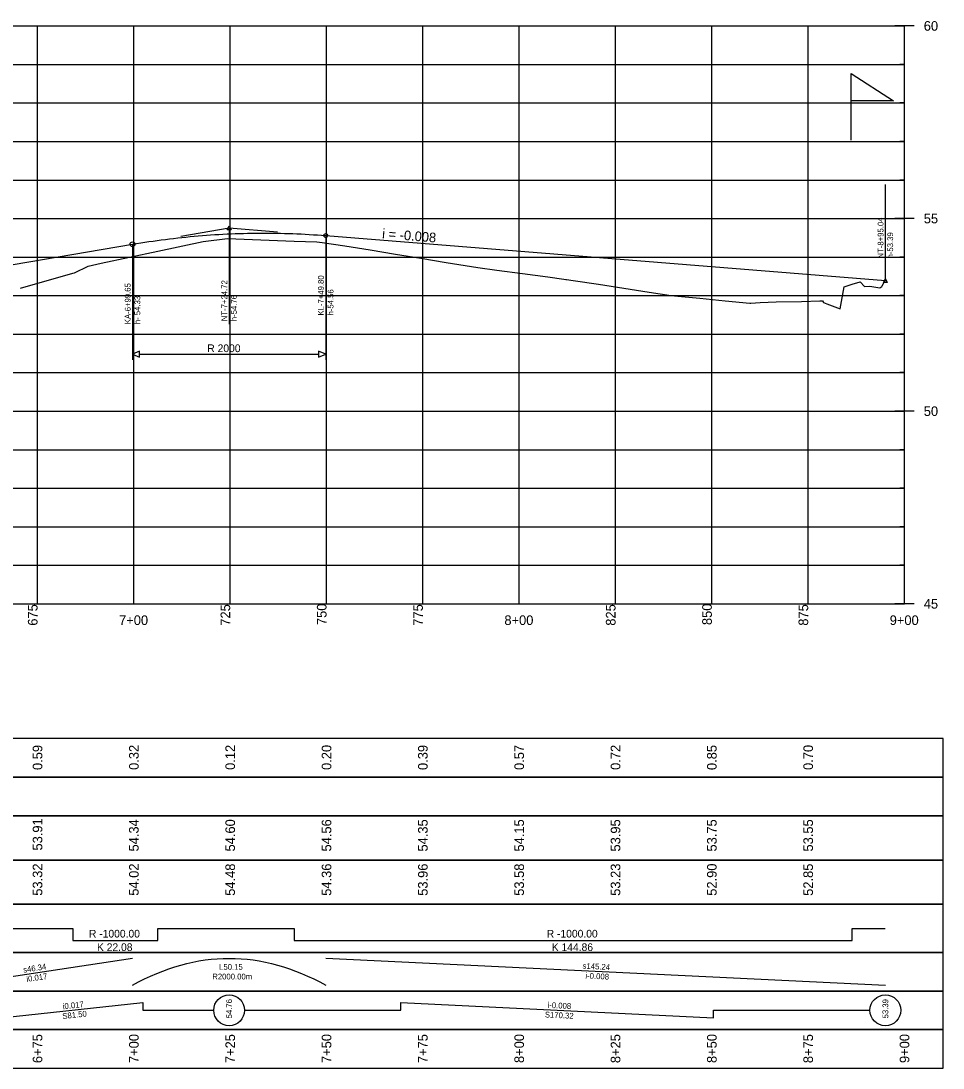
# Model space of a CAD drawing. Extents: x 655100 to 703495, y 6445581 to 6476602.
# Drawn here: x 669980 to 670219.3, y 6465749.1 to 6466020.9 of the extents above; entities that cross this region are included whole.
import ezdxf

# ---------------------------------------------------------------- set-up
doc = ezdxf.new("R2010")
doc.units = 0
for name, color, linetype in [('54', 7, 'Continuous'), ('Level 25', 7, 'Continuous'), ('Level 6', 7, 'Continuous'), ('Profile', 7, 'Continuous'), ('Profile Annotation', 7, 'Continuous'), ('Prop Vertical Alignment', 7, 'Continuous'), ('Prop_Benching', 7, 'Continuous')]:
    doc.layers.add(name, color=color, linetype=linetype)

msp = doc.modelspace()

# ---------------------------------------------------------------- linework, layer by layer
at = {"layer": '54'}
for points in [[(669299.3, 6465824.57), (670219.3, 6465824.57), (670219.3, 6465834.57), (669299.3, 6465834.57)], [(669299.3, 6465814.57), (670219.3, 6465814.57), (670219.3, 6465824.57), (669299.3, 6465824.57)], [(669299.3, 6465803.07), (670219.3, 6465803.07), (670219.3, 6465814.57), (669299.3, 6465814.57)], [(669299.3, 6465791.57), (670219.3, 6465791.57), (670219.3, 6465803.07), (669299.3, 6465803.07)], [(669299.3, 6465779.07), (670219.3, 6465779.07), (670219.3, 6465791.57), (669299.3, 6465791.57)], [(669299.3, 6465769.07), (670219.3, 6465769.07), (670219.3, 6465779.07), (669299.3, 6465779.07)], [(669299.3, 6465759.07), (670219.3, 6465759.07), (670219.3, 6465769.07), (669299.3, 6465769.07)], [(669299.3, 6465749.07), (670219.3, 6465749.07), (670219.3, 6465759.07), (669299.3, 6465759.07)]]:
    msp.add_lwpolyline(points, close=True, dxfattribs=at)
for points in [[(669984.3, 6465834.57), (669984.3, 6465834.57)], [(670009.3, 6465834.57), (670009.3, 6465834.57)], [(670034.3, 6465834.57), (670034.3, 6465834.57)], [(670059.3, 6465834.57), (670059.3, 6465834.57)], [(670084.3, 6465834.57), (670084.3, 6465834.57)], [(670109.3, 6465834.57), (670109.3, 6465834.57)], [(670134.3, 6465834.57), (670134.3, 6465834.57)], [(670159.3, 6465834.57), (670159.3, 6465834.57)], [(670184.3, 6465834.57), (670184.3, 6465834.57)], [(670209.3, 6465834.57), (670209.3, 6465834.57)], [(669984.3, 6465824.57), (669984.3, 6465824.57)], [(670009.3, 6465824.57), (670009.3, 6465824.57)], [(670034.3, 6465824.57), (670034.3, 6465824.57)], [(670059.3, 6465824.57), (670059.3, 6465824.57)], [(670084.3, 6465824.57), (670084.3, 6465824.57)], [(670109.3, 6465824.57), (670109.3, 6465824.57)], [(670134.3, 6465824.57), (670134.3, 6465824.57)], [(670159.3, 6465824.57), (670159.3, 6465824.57)], [(670184.3, 6465824.57), (670184.3, 6465824.57)], [(670209.3, 6465824.57), (670209.3, 6465824.57)], [(669984.3, 6465814.57), (669984.3, 6465814.57)], [(670009.3, 6465814.57), (670009.3, 6465814.57)], [(670034.3, 6465814.57), (670034.3, 6465814.57)], [(670059.3, 6465814.57), (670059.3, 6465814.57)], [(670084.3, 6465814.57), (670084.3, 6465814.57)], [(670109.3, 6465814.57), (670109.3, 6465814.57)], [(670134.3, 6465814.57), (670134.3, 6465814.57)], [(670159.3, 6465814.57), (670159.3, 6465814.57)], [(670184.3, 6465814.57), (670184.3, 6465814.57)], [(670209.3, 6465814.57), (670209.3, 6465814.57)], [(669984.3, 6465803.07), (669984.3, 6465803.07)], [(670009.3, 6465803.07), (670009.3, 6465803.07)], [(670034.3, 6465803.07), (670034.3, 6465803.07)], [(670059.3, 6465803.07), (670059.3, 6465803.07)], [(670084.3, 6465803.07), (670084.3, 6465803.07)], [(670109.3, 6465803.07), (670109.3, 6465803.07)], [(670134.3, 6465803.07), (670134.3, 6465803.07)], [(670159.3, 6465803.07), (670159.3, 6465803.07)], [(670184.3, 6465803.07), (670184.3, 6465803.07)], [(670209.3, 6465803.07), (670209.3, 6465803.07)], [(669993.44, 6465791.57), (669993.44, 6465791.57)], [(670015.52, 6465791.57), (670015.52, 6465791.57)], [(670050.86, 6465791.57), (670050.86, 6465791.57)], [(670195.72, 6465791.57), (670195.72, 6465791.57)], [(670204.27, 6465791.57), (670204.27, 6465791.57)], [(670008.95, 6465779.07), (670008.95, 6465779.07)], [(670059.1, 6465779.07), (670059.1, 6465779.07)], [(670204.34, 6465779.07), (670204.34, 6465779.07)], [(670008.95, 6465769.07), (670008.95, 6465769.07)], [(670059.1, 6465769.07), (670059.1, 6465769.07)], [(670204.34, 6465769.07), (670204.34, 6465769.07)], [(669984.3, 6465759.07), (669984.3, 6465759.07)], [(670009.3, 6465759.07), (670009.3, 6465759.07)], [(670034.3, 6465759.07), (670034.3, 6465759.07)], [(670059.3, 6465759.07), (670059.3, 6465759.07)], [(670084.3, 6465759.07), (670084.3, 6465759.07)], [(670109.3, 6465759.07), (670109.3, 6465759.07)], [(670134.3, 6465759.07), (670134.3, 6465759.07)], [(670159.3, 6465759.07), (670159.3, 6465759.07)], [(670184.3, 6465759.07), (670184.3, 6465759.07)], [(670209.3, 6465759.07), (670209.3, 6465759.07)]]:
    msp.add_lwpolyline(points, dxfattribs=at)
at = {"layer": 'Level 25'}
msp.add_lwpolyline([(670195.42, 6465989.88), (670195.42, 6466007.24), (670206.43, 6466000.16), (670195.41, 6466000.15)], dxfattribs=at)
at = {"layer": 'Level 6'}
msp.add_lwpolyline([(669979.86, 6465951.5), (669993.44, 6465955.39), (669993.92, 6465955.52), (669997.41, 6465957.23), (670000.8, 6465957.97), (670008.16, 6465959.55), (670015.52, 6465961.11), (670027.27, 6465963.57), (670033.61, 6465964.38), (670050.86, 6465963.72), (670056.77, 6465963.49), (670057.44, 6465963.43), (670058.17, 6465963.36), (670061.11, 6465962.96), (670064.03, 6465962.49), (670070.61, 6465961.42), (670077.19, 6465960.34), (670083.78, 6465959.27), (670090.36, 6465958.18), (670096.95, 6465957.1), (670098.54, 6465956.84), (670103.53, 6465956.18), (670110.12, 6465955.3), (670116.7, 6465954.42), (670120.89, 6465953.86), (670121.41, 6465953.79), (670121.57, 6465953.77), (670123.29, 6465953.51), (670129.87, 6465952.5), (670136.46, 6465951.5), (670143.04, 6465950.5), (670148.75, 6465949.63), (670149.62, 6465949.52), (670150.44, 6465949.41), (670156.21, 6465948.87), (670162.79, 6465948.24), (670169.18, 6465947.63), (670169.38, 6465947.64), (670171.83, 6465947.82), (670175.96, 6465947.92), (670182.55, 6465948.07), (670187.32, 6465948.18), (670187.98, 6465948.22), (670188.26, 6465947.74), (670189.13, 6465947.42), (670192.6, 6465946.12), (670193.67, 6465951.83), (670194.97, 6465952.27), (670195.72, 6465952.5), (670197.83, 6465953.18), (670198.88, 6465951.95), (670200.34, 6465952.04), (670202.89, 6465951.61), (670203.39, 6465951.91), (670203.49, 6465952.07), (670204.27, 6465953.46)], dxfattribs=at)
at = {"layer": 'Profile'}
for p, q in [((669309.3, 6466019.57), (670209.3, 6466019.57)), ((669309.3, 6466019.57), (670209.3, 6466019.57)), ((669984.3, 6465869.57), (669984.3, 6466019.57)), ((670009.3, 6465869.57), (670009.3, 6466019.57)), ((670034.3, 6465869.57), (670034.3, 6466019.57)), ((670059.3, 6465869.57), (670059.3, 6466019.57)), ((670084.3, 6465869.57), (670084.3, 6466019.57)), ((670109.3, 6465869.57), (670109.3, 6466019.57)), ((670134.3, 6465869.57), (670134.3, 6466019.57)), ((670159.3, 6465869.57), (670159.3, 6466019.57)), ((670184.3, 6465869.57), (670184.3, 6466019.57)), ((670211.8, 6466019.57), (670206.8, 6466019.57)), ((670211.8, 6466019.57), (670206.8, 6466019.57)), ((670209.3, 6465869.57), (670209.3, 6466019.57)), ((669309.3, 6466009.57), (670209.3, 6466009.57)), ((670209.3, 6466009.57), (670208.05, 6466009.57)), ((669309.3, 6465999.57), (670209.3, 6465999.57)), ((670209.3, 6465999.57), (670208.05, 6465999.57)), ((669309.3, 6465989.57), (670209.3, 6465989.57)), ((670209.3, 6465989.57), (670208.05, 6465989.57)), ((669309.3, 6465979.57), (670209.3, 6465979.57)), ((670209.3, 6465979.57), (670208.05, 6465979.57)), ((669309.3, 6465969.57), (670209.3, 6465969.57)), ((670211.8, 6465969.57), (670206.8, 6465969.57)), ((669309.3, 6465959.57), (670209.3, 6465959.57)), ((670209.3, 6465959.57), (670208.05, 6465959.57)), ((669309.3, 6465949.57), (670209.3, 6465949.57)), ((670209.3, 6465949.57), (670208.05, 6465949.57)), ((669309.3, 6465939.57), (670209.3, 6465939.57)), ((670209.3, 6465939.57), (670208.05, 6465939.57)), ((669309.3, 6465929.57), (670209.3, 6465929.57)), ((670209.3, 6465929.57), (670208.05, 6465929.57)), ((669309.3, 6465919.57), (670209.3, 6465919.57)), ((670211.8, 6465919.57), (670206.8, 6465919.57)), ((669309.3, 6465909.57), (670209.3, 6465909.57)), ((670209.3, 6465909.57), (670208.05, 6465909.57)), ((669309.3, 6465899.57), (670209.3, 6465899.57)), ((670209.3, 6465899.57), (670208.05, 6465899.57)), ((669309.3, 6465889.57), (670209.3, 6465889.57)), ((670209.3, 6465889.57), (670208.05, 6465889.57)), ((669309.3, 6465879.57), (670209.3, 6465879.57)), ((670209.3, 6465879.57), (670208.05, 6465879.57)), ((669309.3, 6465869.57), (670209.3, 6465869.57)), ((670211.8, 6465869.57), (670206.8, 6465869.57))]:
    msp.add_line(p, q, dxfattribs=at)
at = {"layer": 'Profile Annotation'}
for points in [[(669648.62, 6465785.32), (669796.34, 6465785.32), (669796.34, 6465782.2), (669823.91, 6465782.2), (669823.91, 6465785.32), (669845.97, 6465785.32), (669845.97, 6465788.45), (669881.07, 6465788.45), (669881.07, 6465785.32), (669930.74, 6465785.32), (669930.74, 6465782.2), (669941.56, 6465782.2), (669941.56, 6465785.32), (669993.44, 6465785.32), (669993.44, 6465782.2), (670015.52, 6465782.2), (670015.52, 6465785.32), (670050.86, 6465785.32), (670050.86, 6465782.2), (670195.72, 6465782.2), (670195.72, 6465785.32), (670204.27, 6465785.32)], [(669962.61, 6465770.57), (670008.95, 6465777.57)], [(670008.95, 6465770.57), (670010.52, 6465771.42), (670012.09, 6465772.21), (670013.65, 6465772.95), (670015.22, 6465773.64), (670016.79, 6465774.26), (670018.35, 6465774.84), (670019.92, 6465775.36), (670021.49, 6465775.82), (670023.06, 6465776.23), (670024.62, 6465776.59), (670026.19, 6465776.89), (670027.76, 6465777.14), (670029.32, 6465777.33), (670030.89, 6465777.46), (670032.46, 6465777.55), (670035.59, 6465777.55), (670037.16, 6465777.46), (670038.73, 6465777.33), (670040.29, 6465777.14), (670041.86, 6465776.89), (670043.43, 6465776.59), (670045, 6465776.23), (670046.56, 6465775.82), (670048.13, 6465775.36), (670049.7, 6465774.84), (670051.26, 6465774.26), (670052.83, 6465773.64), (670054.4, 6465772.95), (670055.97, 6465772.21), (670057.53, 6465771.42), (670059.1, 6465770.57)], [(670059.1, 6465777.57), (670204.34, 6465770.57)], [(669956.52, 6465764.07), (669974.9, 6465764.07), (669974.9, 6465762.07), (670011.65, 6465766.07), (670011.65, 6465764.07), (670030.02, 6465764.07)], [(670038.02, 6465764.07), (670078.6, 6465764.07), (670078.6, 6465766.07), (670159.76, 6465762.07), (670159.76, 6465764.07), (670200.34, 6465764.07)]]:
    msp.add_lwpolyline(points, dxfattribs=at)
for centre in [(670034.02, 6465764.07), (670204.34, 6465764.07)]:
    msp.add_circle(centre, 4, dxfattribs=at)
at = {"layer": 'Prop Vertical Alignment'}
for p, q in [((670204.34, 6465958.45), (670204.34, 6465978.45)), ((670021.49, 6465965.03), (670034.02, 6465967.17)), ((670034.02, 6465967.17), (670046.56, 6465966.16)), ((670034.02, 6465967.17), (670034.02, 6465962.17)), ((670059.1, 6465965.15), (670059.1, 6465960.15)), ((670059.1, 6465965.15), (670204.34, 6465953.45)), ((670059.1, 6465965.15), (670059.1, 6465932.9)), ((669962.61, 6465955.01), (670008.95, 6465962.9)), ((670008.95, 6465962.9), (670008.95, 6465957.9)), ((670008.95, 6465962.9), (670008.95, 6465932.9)), ((670034.02, 6465962.17), (670034.02, 6465942.17)), ((670008.95, 6465957.9), (670008.95, 6465941.4)), ((670059.1, 6465960.15), (670059.1, 6465943.65)), ((670204.34, 6465953.45), (670204.34, 6465958.45))]:
    msp.add_line(p, q, dxfattribs=at)
for points in [[(670008.95, 6465962.9), (670010.02, 6465963.08), (670011.08, 6465963.25), (670012.15, 6465963.42), (670013.22, 6465963.58), (670014.29, 6465963.74), (670015.35, 6465963.89), (670016.42, 6465964.03), (670017.49, 6465964.17), (670018.55, 6465964.3), (670019.62, 6465964.43), (670020.69, 6465964.55), (670021.75, 6465964.67), (670022.82, 6465964.78), (670023.89, 6465964.88), (670024.96, 6465964.98), (670026.02, 6465965.08), (670027.09, 6465965.16), (670028.16, 6465965.25), (670029.22, 6465965.32), (670030.29, 6465965.39), (670031.36, 6465965.46), (670032.42, 6465965.52), (670033.49, 6465965.57), (670034.56, 6465965.62), (670035.63, 6465965.66), (670036.69, 6465965.7), (670037.76, 6465965.73), (670038.83, 6465965.75), (670039.89, 6465965.77), (670040.96, 6465965.78), (670042.03, 6465965.79), (670043.09, 6465965.8), (670044.16, 6465965.79), (670045.23, 6465965.78), (670046.3, 6465965.77), (670047.36, 6465965.75), (670048.43, 6465965.72), (670049.5, 6465965.69), (670050.56, 6465965.65), (670051.63, 6465965.61), (670052.7, 6465965.56), (670053.77, 6465965.5), (670054.83, 6465965.44), (670055.9, 6465965.38), (670056.97, 6465965.31), (670058.03, 6465965.23), (670059.1, 6465965.15)], [(670010.8, 6465934.4), (670057.25, 6465934.4)]]:
    msp.add_lwpolyline(points, dxfattribs=at)
for points in [[(670034.02, 6465967.67), (670034.52, 6465966.67), (670033.52, 6465966.67)], [(670204.34, 6465953.95), (670204.84, 6465952.95), (670203.84, 6465952.95)], [(670008.95, 6465934.4), (670010.8, 6465933.63), (670010.8, 6465935.16)], [(670059.1, 6465934.4), (670057.25, 6465935.16), (670057.25, 6465933.63)]]:
    msp.add_lwpolyline(points, close=True, dxfattribs=at)
for centre, radius in [((670008.95, 6465962.9), 0.625), ((670059.1, 6465965.15), 0.5)]:
    msp.add_circle(centre, radius, dxfattribs=at)

# ---------------------------------------------------------------- texts
at = {"layer": 'Profile'}
for s, p in [('60', (670214.3, 6466018.32)), ('60', (670214.3, 6466018.32)), ('55', (670214.3, 6465968.32)), ('50', (670214.3, 6465918.32)), ('45', (670214.3, 6465868.32)), ('7+00', (670005.46, 6465864.07)), ('8+00', (670105.46, 6465864.07)), ('9+00', (670205.46, 6465864.07))]:
    msp.add_text(s, height=2.5, dxfattribs=at).set_placement(p)
for s, p in [('675', (669984.3, 6465863.89)), ('725', (670034.3, 6465863.89)), ('750', (670059.3, 6465864.05)), ('775', (670084.3, 6465863.89)), ('825', (670134.3, 6465863.89)), ('850', (670159.3, 6465864.05)), ('875', (670184.3, 6465863.89))]:
    msp.add_text(s, height=2.5, rotation=90, dxfattribs=at).set_placement(p)
at = {"layer": 'Profile Annotation'}
for s, height, rotation, p in [('0.59', 2.5, 90, (669985.55, 6465826.43)), ('0.32', 2.5, 90, (670010.55, 6465826.46)), ('0.12', 2.5, 90, (670035.55, 6465826.46)), ('0.20', 2.5, 90, (670060.55, 6465826.45)), ('0.39', 2.5, 90, (670085.55, 6465826.43)), ('0.57', 2.5, 90, (670110.55, 6465826.44)), ('0.72', 2.5, 90, (670135.55, 6465826.46)), ('0.85', 2.5, 90, (670160.55, 6465826.42)), ('0.70', 2.5, 90, (670185.55, 6465826.45)), ('53.91', 2.5, 90, (669985.55, 6465805.53)), ('54.34', 2.5, 90, (670010.55, 6465805.29)), ('54.60', 2.5, 90, (670035.55, 6465805.29)), ('54.56', 2.5, 90, (670060.55, 6465805.28)), ('54.35', 2.5, 90, (670085.55, 6465805.27)), ('54.15', 2.5, 90, (670110.55, 6465805.27)), ('53.95', 2.5, 90, (670135.55, 6465805.27)), ('53.75', 2.5, 90, (670160.55, 6465805.27)), ('53.55', 2.5, 90, (670185.55, 6465805.27)), ('53.32', 2.5, 90, (669985.55, 6465793.8)), ('54.02', 2.5, 90, (670010.55, 6465793.8)), ('54.48', 2.5, 90, (670035.55, 6465793.78)), ('54.36', 2.5, 90, (670060.55, 6465793.78)), ('53.96', 2.5, 90, (670085.55, 6465793.78)), ('53.58', 2.5, 90, (670110.55, 6465793.78)), ('53.23', 2.5, 90, (670135.55, 6465793.78)), ('52.90', 2.5, 90, (670160.55, 6465793.79)), ('52.85', 2.5, 90, (670185.55, 6465793.77)), ('s46.34', 1.5, 8.5896, (669980.69, 6465773.81)), ('s145.24', 1.5, 357.2407, (670125.72, 6465774.86)), ('i0.017', 1.5, 8.5896, (669981.53, 6465771.41)), ('i-0.008', 1.5, 357.2407, (670126.45, 6465772.32)), ('i0.017', 1.5, 6.2115, (669990.93, 6465764.32)), ('54.76', 1.5, 90, (670034.77, 6465761.96)), ('i-0.008', 1.5, 357.1784, (670116.62, 6465764.7)), ('53.39', 1.5, 90, (670205.09, 6465761.96)), ('S81.50', 1.5, 6.2115, (669990.82, 6465761.79)), ('S170.32', 1.5, 357.1784, (670115.93, 6465762.23)), ('6+75', 2.5, 90, (669985.55, 6465750.35)), ('7+00', 2.5, 90, (670010.55, 6465750.38)), ('7+25', 2.5, 90, (670035.55, 6465750.35)), ('7+50', 2.5, 90, (670060.55, 6465750.38)), ('7+75', 2.5, 90, (670085.55, 6465750.35)), ('8+00', 2.5, 90, (670110.55, 6465750.38)), ('8+25', 2.5, 90, (670135.55, 6465750.35)), ('8+50', 2.5, 90, (670160.55, 6465750.38)), ('8+75', 2.5, 90, (670185.55, 6465750.35)), ('9+00', 2.5, 90, (670210.55, 6465750.38))]:
    msp.add_text(s, height=height, rotation=rotation, dxfattribs=at).set_placement(p)
for s, p in [('L50.15', (670031.43, 6465774.57)), ('R2000.00m', (670029.64, 6465772.07))]:
    msp.add_text(s, height=1.5, dxfattribs=at).set_placement(p)
at = {"layer": 'Prop Vertical Alignment'}
for s, height, rotation, p in [('NT-8+95.04', 1.5, 90, (670203.84, 6465959.2)), ('i = -0.008', 2.5, 355.3942, (670073.66, 6465964.47)), ('h-53.39', 1.5, 90, (670206.34, 6465959.2)), ('KA-6+99.65', 1.5, 90, (670008.45, 6465942.15)), ('NT-7+24.72', 1.5, 90, (670033.52, 6465942.92)), ('KL-7+49.80', 1.5, 90, (670058.6, 6465944.4)), ('h- 54.33', 1.5, 90, (670010.95, 6465942.15)), ('h-54.76', 1.5, 90, (670036.02, 6465942.92)), ('h-54.56', 1.5, 90, (670061.1, 6465944.4))]:
    msp.add_text(s, height=height, rotation=rotation, dxfattribs=at).set_placement(p)
msp.add_text('R 2000', height=2, dxfattribs=at).set_placement((670028.36, 6465934.9))
at = {"layer": 'Prop_Benching'}
for s, p in [('R -1000.00', (669997.64, 6465782.95)), ('R -1000.00', (670116.44, 6465782.95)), ('K 22.08', (669999.73, 6465779.45)), ('K 144.86', (670117.76, 6465779.45))]:
    msp.add_text(s, height=2, dxfattribs=at).set_placement(p)

doc.saveas('drawing.dxf')
